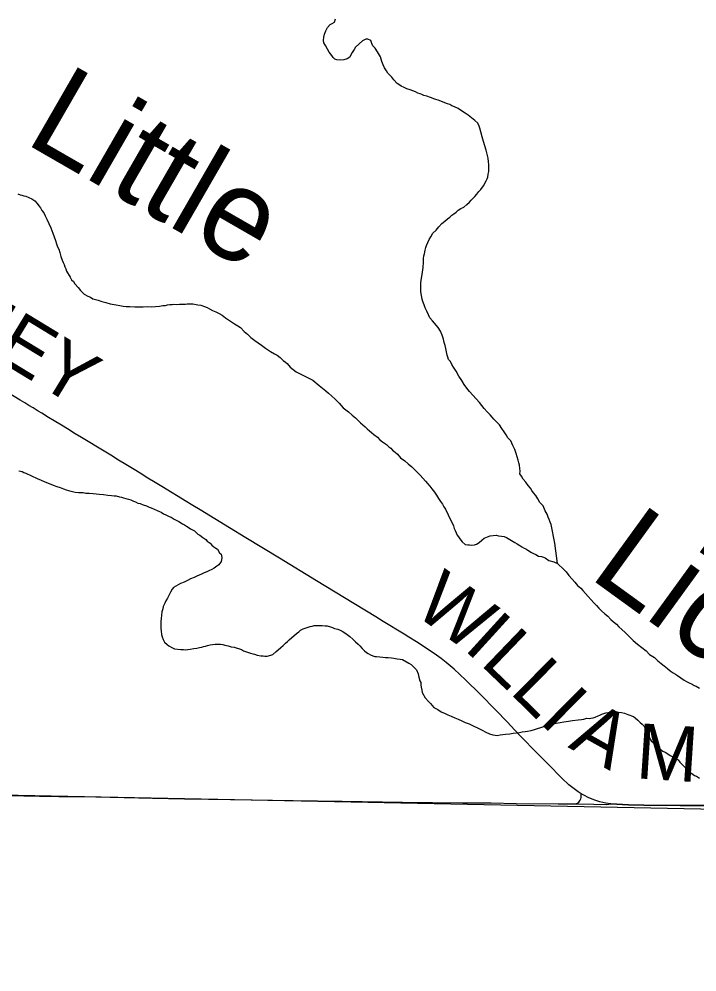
# Model space of a CAD drawing. Extents: x 0 to 34, y 0 to 22.
# Drawn here: x 5.756 to 6.454, y 15.275 to 16.256 of the extents above; entities that cross this region are included whole.
import ezdxf

# ---------------------------------------------------------------- set-up
doc = ezdxf.new("R2010")
doc.units = 0
for name, color, linetype in [('GM_X_County_Road', 7, 'Continuous'), ('GM_X_County_Road_Text', 7, 'Continuous'), ('GM_X_Minor_River', 7, 'Continuous'), ('GM_X_Minor_River_Text', 7, 'Continuous'), ('GM_X_Section', 7, 'Continuous'), ('GM_X_Township_Road', 7, 'Continuous')]:
    doc.layers.add(name, color=color, linetype=linetype)

msp = doc.modelspace()

# ---------------------------------------------------------------- linework, layer by layer
at = {"layer": 'GM_X_County_Road'}
for points in [[(6.33483, 15.45839), (6.33171, 15.46046), (6.32761, 15.46337), (6.32224, 15.46771), (6.31492, 15.47452), (6.3009, 15.48869), (6.28479, 15.50511), (6.27696, 15.51311), (6.27176, 15.51845), (6.26618, 15.52429), (6.26273, 15.52789), (6.25845, 15.53239), (6.24682, 15.54447), (6.23072, 15.56089), (6.21575, 15.57578), (6.2039, 15.58673), (6.19591, 15.59358), (6.19058, 15.59778), (6.18347, 15.60274), (6.16532, 15.61467), (6.1574, 15.61957), (6.15264, 15.6225), (6.13094, 15.63585), (6.1235, 15.64038), (6.09109, 15.66007), (6.06245, 15.67757), (6.02423, 15.70089), (5.98969, 15.72186), (5.97273, 15.73227), (5.94246, 15.75068), (5.93499, 15.75516), (5.92703, 15.76), (5.92012, 15.7642), (5.91219, 15.76909), (5.90475, 15.7736), (5.89628, 15.7788), (5.88886, 15.78336), (5.88092, 15.78824), (5.87455, 15.7921), (5.8661, 15.79735), (5.85868, 15.80189), (5.85073, 15.80676), (5.84383, 15.81096), (5.83534, 15.81614), (5.82896, 15.82), (5.82046, 15.82517), (5.81407, 15.82901), (5.8061, 15.83384), (5.79973, 15.83773), (5.79231, 15.84227), (5.78647, 15.84583), (5.77959, 15.85005), (5.77588, 15.85232), (5.77057, 15.85555), (5.76632, 15.8581), (5.76207, 15.86067), (5.75728, 15.86356), (5.72112, 15.88545)], [(5.621, 15.45844), (5.66541, 15.45788), (5.68717, 15.45771), (5.74498, 15.45665), (5.7773, 15.45592), (5.79719, 15.45568), (5.82082, 15.45543), (5.89354, 15.45403), (5.92648, 15.45322), (5.95134, 15.4527), (5.9961, 15.45214), (6.03837, 15.45131), (6.08872, 15.45092), (6.15088, 15.44988), (6.21305, 15.44908), (6.24227, 15.44895), (6.26775, 15.44848), (6.31127, 15.44811), (6.32904, 15.44791)], [(6.36524, 15.44799), (6.36004, 15.44883), (6.35391, 15.45026), (6.34792, 15.45217), (6.34211, 15.45459), (6.33824, 15.4566), (6.33483, 15.45839)], [(6.32904, 15.44791), (6.34795, 15.44764), (6.36076, 15.44734), (6.36315, 15.44759), (6.36524, 15.44799)], [(6.63564, 15.44407), (6.62493, 15.44411), (6.60569, 15.44445), (6.58518, 15.44447), (6.55657, 15.44478), (6.49876, 15.44583), (6.46705, 15.44615), (6.43659, 15.44644), (6.39929, 15.44676), (6.38362, 15.4471), (6.36524, 15.44799)]]:
    msp.add_lwpolyline(points, dxfattribs=at)
at = {"layer": 'GM_X_Minor_River'}
for points in [[(6.20369, 16.05524), (6.20601, 16.05709), (6.20833, 16.05893), (6.21103, 16.06077), (6.2141, 16.06221), (6.2172, 16.0648), (6.21992, 16.06739), (6.22148, 16.06926), (6.22342, 16.07111), (6.22536, 16.07296), (6.22732, 16.07557), (6.22928, 16.07818), (6.23161, 16.08041), (6.23318, 16.08265), (6.23475, 16.08451), (6.23556, 16.08677), (6.23714, 16.08939), (6.23794, 16.09127), (6.23874, 16.09316), (6.2392, 16.09618), (6.23964, 16.09883), (6.23969, 16.10111), (6.23976, 16.10414), (6.23981, 16.10604), (6.23949, 16.10871), (6.2392, 16.11252), (6.23816, 16.11672), (6.23712, 16.12092), (6.2357, 16.12513), (6.23429, 16.12973), (6.23289, 16.1347), (6.23148, 16.13967), (6.23044, 16.14349), (6.22972, 16.14541), (6.22828, 16.14848), (6.2253, 16.15121), (6.2186, 16.15669), (6.21524, 16.15905), (6.2115, 16.16142), (6.20813, 16.16378), (6.20437, 16.16538), (6.20175, 16.16659), (6.1995, 16.16778), (6.19724, 16.16859), (6.19272, 16.17022), (6.18858, 16.17184), (6.18407, 16.17347), (6.17955, 16.17509), (6.17578, 16.17632), (6.17276, 16.17716), (6.17088, 16.17796), (6.16901, 16.17876), (6.16675, 16.17958), (6.16412, 16.18078), (6.16149, 16.18198), (6.15885, 16.1828), (6.15546, 16.18402), (6.15245, 16.18523), (6.14945, 16.18682), (6.14721, 16.1884), (6.14534, 16.18958), (6.14201, 16.19308), (6.13979, 16.19579), (6.13758, 16.1985), (6.13572, 16.20007), (6.13425, 16.20238), (6.13243, 16.20546), (6.13098, 16.20854), (6.12954, 16.21199), (6.12814, 16.21696), (6.12522, 16.22197), (6.12266, 16.22583), (6.12043, 16.22816), (6.11935, 16.23046), (6.11828, 16.23353), (6.11528, 16.23512), (6.11301, 16.23517), (6.10955, 16.23336), (6.10255, 16.22669), (6.10098, 16.22444), (6.09902, 16.22145), (6.09781, 16.21882), (6.09662, 16.21657), (6.09392, 16.21474), (6.09048, 16.21368), (6.08668, 16.21339), (6.08327, 16.21385), (6.08139, 16.21465), (6.07953, 16.21622), (6.07806, 16.21815), (6.07548, 16.22163), (6.07365, 16.22471), (6.07147, 16.22856), (6.07001, 16.23126), (6.06969, 16.23355), (6.06977, 16.23696), (6.07061, 16.24036), (6.07183, 16.24375), (6.0738, 16.24712), (6.07653, 16.2501), (6.07845, 16.25119)], [(6.07845, 16.25119), (6.08077, 16.25265), (6.08198, 16.25604)], [(5.75505, 16.07579), (5.75731, 16.07498), (5.7592, 16.07456), (5.76108, 16.07375), (5.76335, 16.07332), (5.76636, 16.0721), (5.76937, 16.07089), (5.77235, 16.06854), (5.77494, 16.06582), (5.77641, 16.06351), (5.77826, 16.06156), (5.77971, 16.05887), (5.78155, 16.05617), (5.783, 16.0531), (5.78481, 16.04963), (5.78699, 16.0454), (5.78878, 16.0408), (5.79093, 16.03543), (5.79236, 16.0316), (5.79379, 16.02777), (5.79485, 16.02432), (5.79591, 16.02126), (5.797, 16.01895), (5.79806, 16.01551), (5.7991, 16.01131), (5.80053, 16.00747), (5.80161, 16.00517), (5.8027, 16.00324), (5.8034, 16.00057), (5.8045, 15.99864), (5.8052, 15.99635), (5.80885, 15.99018), (5.81031, 15.98749)], [(6.30782, 15.71634), (6.304, 15.73565), (6.30291, 15.73795), (6.30183, 15.74064), (6.30075, 15.74294), (6.29968, 15.74601), (6.29787, 15.74947), (6.29572, 15.75484), (6.29238, 15.75834), (6.29018, 15.76181), (6.28799, 15.76528), (6.28577, 15.76799), (6.28394, 15.7707), (6.28247, 15.77301), (6.28026, 15.77572), (6.27769, 15.7792), (6.2751, 15.7823), (6.27327, 15.78539), (6.27181, 15.7877), (6.27187, 15.79036), (6.27156, 15.79303), (6.27126, 15.79645), (6.27056, 15.79913), (6.26986, 15.8018), (6.2688, 15.80525), (6.26775, 15.80869), (6.26633, 15.8129), (6.26452, 15.81675), (6.26236, 15.82174), (6.2594, 15.82485), (6.25757, 15.82793), (6.25537, 15.83102), (6.25317, 15.83449), (6.25059, 15.83797), (6.24763, 15.84108), (6.24504, 15.8438), (6.24319, 15.84613), (6.24097, 15.84846), (6.238, 15.85157), (6.23505, 15.85506), (6.23026, 15.86125), (6.2199, 15.87251), (6.21694, 15.876), (6.21436, 15.87948), (6.2118, 15.88372), (6.20888, 15.88835), (6.20596, 15.89336), (6.2034, 15.8976), (6.20157, 15.9003), (6.20012, 15.90338), (6.19826, 15.90532), (6.19756, 15.90762), (6.19686, 15.90991), (6.19618, 15.91335), (6.1955, 15.91678), (6.19481, 15.91984), (6.19374, 15.9229), (6.19306, 15.92634), (6.19165, 15.93055), (6.18984, 15.93439), (6.18765, 15.93824), (6.18396, 15.94289), (6.18174, 15.94522), (6.17915, 15.94832), (6.17771, 15.9514), (6.1759, 15.95524), (6.17408, 15.9587), (6.17302, 15.96177), (6.17196, 15.96521), (6.17125, 15.96751), (6.17058, 15.97132), (6.16991, 15.97513), (6.1696, 15.9778), (6.16966, 15.98046), (6.16974, 15.98388), (6.17019, 15.9869), (6.17066, 15.99069), (6.17153, 15.99523), (6.17202, 16.00016), (6.17253, 16.00546), (6.17261, 16.00926), (6.17268, 16.01192), (6.17349, 16.01418), (6.17434, 16.01796), (6.17478, 16.0206), (6.17559, 16.02286), (6.17839, 16.02887), (6.17997, 16.0315), (6.18196, 16.03525), (6.18545, 16.03858), (6.18819, 16.04194), (6.1913, 16.04528), (6.1944, 16.04787), (6.19711, 16.05008), (6.19943, 16.05193), (6.20175, 16.05377), (6.20369, 16.05524)], [(5.81031, 15.98749), (5.81216, 15.98554), (5.81362, 15.98323), (5.81695, 15.97935), (5.81954, 15.97625), (5.82325, 15.97274), (5.82699, 15.97038), (5.82963, 15.96956), (5.83225, 15.96797), (5.83488, 15.96715), (5.83752, 15.96633), (5.84129, 15.9651), (5.84544, 15.96386), (5.84997, 15.96261), (5.85602, 15.96171), (5.85979, 15.96086), (5.8632, 15.9604), (5.86661, 15.95994), (5.8704, 15.95985), (5.87533, 15.95973), (5.87989, 15.95962), (5.88406, 15.95952), (5.88862, 15.9598), (5.89279, 15.9597), (5.8966, 15.95998), (5.90078, 15.96026), (5.90421, 15.96094), (5.90687, 15.96088), (5.90916, 15.96159), (5.91145, 15.96191), (5.91373, 15.96186), (5.91563, 15.96219), (5.91829, 15.96213), (5.92133, 15.96244), (5.92475, 15.96235), (5.9274, 15.96229), (5.92931, 15.96263), (5.93121, 15.96258), (5.9331, 15.96254), (5.935, 15.96249), (5.93841, 15.96203), (5.94029, 15.9616), (5.94332, 15.96115), (5.94709, 15.95992), (5.94972, 15.95872), (5.95235, 15.95752), (5.95535, 15.95593), (5.95873, 15.95433), (5.96211, 15.95273), (5.96511, 15.95114), (5.96884, 15.94839), (5.97369, 15.94486), (5.9778, 15.9421), (5.98155, 15.94011), (5.98416, 15.93815), (5.98787, 15.93426), (5.99122, 15.93152), (5.99493, 15.92801), (5.99904, 15.92488), (6.0024, 15.92252), (6.00576, 15.92016), (6.00986, 15.91702), (6.01509, 15.91348), (6.01921, 15.9111), (6.02184, 15.9099), (6.02482, 15.90755), (6.02817, 15.90443), (6.0304, 15.90248), (6.03227, 15.90129), (6.03522, 15.89742), (6.04156, 15.89271), (6.04756, 15.88953), (6.05169, 15.88754), (6.05582, 15.88554), (6.05844, 15.88395), (6.06068, 15.88238), (6.06291, 15.88043), (6.06514, 15.87848), (6.0685, 15.87574), (6.07185, 15.873), (6.07483, 15.87065), (6.0778, 15.86792), (6.08152, 15.86441), (6.0856, 15.86052), (6.08966, 15.85548), (6.09526, 15.85155), (6.09897, 15.84804), (6.10233, 15.8453), (6.1053, 15.84257), (6.10752, 15.84024), (6.11013, 15.83828), (6.11236, 15.83595), (6.11459, 15.83399), (6.11682, 15.83204), (6.11905, 15.83009), (6.12129, 15.82814), (6.12502, 15.82539), (6.12761, 15.82266), (6.13022, 15.8207), (6.13246, 15.81913), (6.13433, 15.81795)], [(6.13433, 15.81795), (6.13694, 15.81561), (6.1388, 15.81404), (6.14065, 15.8121), (6.14326, 15.81014), (6.14586, 15.8078), (6.14882, 15.80431), (6.1533, 15.80116), (6.15664, 15.79804), (6.16037, 15.79491), (6.1689, 15.78635), (6.17186, 15.78324), (6.17444, 15.78014), (6.17667, 15.77781), (6.17888, 15.7751), (6.1811, 15.77238), (6.18367, 15.76891), (6.18588, 15.76581), (6.18807, 15.76234), (6.1899, 15.75926), (6.19211, 15.75655), (6.19357, 15.75385), (6.19503, 15.75116), (6.19611, 15.74885), (6.19757, 15.74654), (6.19829, 15.74462), (6.19974, 15.74193), (6.20081, 15.73886), (6.20227, 15.73655), (6.20336, 15.73424), (6.20405, 15.73157), (6.20514, 15.72926), (6.20622, 15.72696), (6.20731, 15.72465), (6.2084, 15.72273), (6.20988, 15.72079), (6.21246, 15.71769), (6.21544, 15.71496), (6.21808, 15.71452), (6.21998, 15.71447), (6.22226, 15.71442), (6.22492, 15.71473), (6.22721, 15.71544), (6.2299, 15.7169), (6.23262, 15.71949), (6.23494, 15.72134), (6.2384, 15.72277), (6.24108, 15.72385), (6.24412, 15.72416), (6.24717, 15.72446), (6.24981, 15.72402), (6.25284, 15.72357), (6.25549, 15.72313), (6.25775, 15.72231), (6.25962, 15.72113), (6.26636, 15.71717), (6.26898, 15.71559), (6.2716, 15.714), (6.27384, 15.71243), (6.27609, 15.71124), (6.27797, 15.71043), (6.27984, 15.70925), (6.28358, 15.70688), (6.28583, 15.70569), (6.28808, 15.70449), (6.2907, 15.70291), (6.2941, 15.70245), (6.29599, 15.70202), (6.29787, 15.70122), (6.3016, 15.69847), (6.30651, 15.69721), (6.31026, 15.69523), (6.31696, 15.68937), (6.31917, 15.68666), (6.32212, 15.68317), (6.32545, 15.67929), (6.32841, 15.67618), (6.33099, 15.6727), (6.33434, 15.66996), (6.33656, 15.66763), (6.33915, 15.66452), (6.34211, 15.66141), (6.34507, 15.65792), (6.34765, 15.65482), (6.35063, 15.65209), (6.35284, 15.64938), (6.35581, 15.64665), (6.35916, 15.64353), (6.36214, 15.64118), (6.36547, 15.63768), (6.36808, 15.63534), (6.37106, 15.63299), (6.37365, 15.63027), (6.37662, 15.62754), (6.37997, 15.62442), (6.38367, 15.62053), (6.38813, 15.61625), (6.39259, 15.61234), (6.39706, 15.60882), (6.40154, 15.60567), (6.40525, 15.60178)], [(5.75596, 15.79085), (5.75935, 15.79001), (5.76123, 15.78921), (5.76311, 15.7884), (5.77475, 15.78281), (5.77889, 15.78119), (5.78265, 15.77958), (5.78715, 15.77757), (5.79129, 15.77595), (5.79506, 15.77473), (5.79845, 15.77351), (5.80184, 15.77228), (5.80485, 15.77107), (5.80711, 15.77064), (5.80937, 15.76983), (5.81126, 15.7694), (5.81391, 15.76896), (5.81731, 15.7685), (5.81921, 15.76845), (5.82225, 15.76838), (5.82489, 15.76794), (5.82831, 15.76786), (5.83247, 15.76738), (5.83853, 15.76685), (5.84308, 15.76637), (5.84762, 15.76588), (5.85141, 15.76541), (5.85405, 15.76497)], [(5.85405, 15.76497), (5.85633, 15.76491), (5.85973, 15.76407), (5.86162, 15.76365), (5.86387, 15.76283), (5.86614, 15.7624), (5.86878, 15.76158), (5.87142, 15.76076), (5.87405, 15.75955), (5.87593, 15.75875), (5.87856, 15.75755), (5.88083, 15.75711), (5.88383, 15.7559), (5.88722, 15.75468), (5.89023, 15.75347), (5.89211, 15.75266), (5.8985, 15.74985), (5.90076, 15.74904), (5.90264, 15.74823), (5.90488, 15.74666), (5.90713, 15.74547), (5.91088, 15.74386), (5.91276, 15.74306), (5.91576, 15.74109), (5.91801, 15.73989), (5.92064, 15.73869), (5.92437, 15.73632), (5.92662, 15.73513), (5.9285, 15.73395), (5.93037, 15.73276), (5.93261, 15.73119), (5.93486, 15.72999), (5.93674, 15.72919), (5.94007, 15.72569), (5.94232, 15.7245), (5.9453, 15.72215), (5.94829, 15.72018), (5.94977, 15.71824), (5.95276, 15.71627), (5.95461, 15.71433), (5.95684, 15.71238), (5.95871, 15.71119), (5.96058, 15.71001), (5.9624, 15.70654), (5.96426, 15.70498), (5.96494, 15.70154), (5.96451, 15.69927), (5.96408, 15.69739), (5.96172, 15.69402), (5.95979, 15.69255), (5.95709, 15.69071), (5.95478, 15.68925), (5.95171, 15.6878), (5.9494, 15.68672), (5.94672, 15.68564), (5.94404, 15.68456), (5.94174, 15.68348), (5.93905, 15.68241), (5.93636, 15.68095), (5.93253, 15.67952), (5.92946, 15.67807), (5.926, 15.67626), (5.92255, 15.67482), (5.91986, 15.67336), (5.91755, 15.6719), (5.91525, 15.67081), (5.91368, 15.66895), (5.91209, 15.66595), (5.9105, 15.66257), (5.90891, 15.65956), (5.90733, 15.65694), (5.90613, 15.65469), (5.90454, 15.65131), (5.90409, 15.64866), (5.90326, 15.64564), (5.9028, 15.64223), (5.90234, 15.63882), (5.90227, 15.63579), (5.90218, 15.63199), (5.90211, 15.62895), (5.90242, 15.62591), (5.90272, 15.62248), (5.90342, 15.6198), (5.90449, 15.61712), (5.90595, 15.61442), (5.90855, 15.61208), (5.91041, 15.61052), (5.91416, 15.60853), (5.91604, 15.60773), (5.92285, 15.6068), (5.92551, 15.60674), (5.92778, 15.60669), (5.93007, 15.60701), (5.93236, 15.60734), (5.93617, 15.60801), (5.93921, 15.60831), (5.94189, 15.60901), (5.94417, 15.60934), (5.94609, 15.61005), (5.94799, 15.61038), (5.95029, 15.61109)], [(6.31026, 15.69523), (6.30782, 15.71634)], [(5.95029, 15.61109), (5.95296, 15.61179), (5.95525, 15.61211), (5.95791, 15.61243), (5.96057, 15.61237), (5.9636, 15.61229), (5.96587, 15.61186), (5.96814, 15.61143), (5.97154, 15.61059), (5.97455, 15.60975), (5.97758, 15.6093), (5.97984, 15.60849), (5.98323, 15.60765), (5.98512, 15.60684), (5.98736, 15.60565), (5.99037, 15.60444), (5.99452, 15.6032), (5.99678, 15.60239), (5.99867, 15.60196), (6.0013, 15.60114), (6.00508, 15.60029), (6.00736, 15.60024), (6.00926, 15.60019), (6.01153, 15.60014), (6.01535, 15.60119), (6.01727, 15.6019), (6.02075, 15.60486), (6.02307, 15.6067), (6.02578, 15.60892), (6.02812, 15.61114), (6.03044, 15.61336), (6.03239, 15.61522), (6.03432, 15.61669), (6.04169, 15.62336), (6.04401, 15.6252), (6.04594, 15.62667), (6.04863, 15.62813), (6.0559, 15.63062), (6.05781, 15.63095), (6.06011, 15.63166), (6.062, 15.63161), (6.0658, 15.63152), (6.06807, 15.63147), (6.07111, 15.63139), (6.07338, 15.63134), (6.07677, 15.63012), (6.07866, 15.62969), (6.08091, 15.6285), (6.08431, 15.62766), (6.08657, 15.62685), (6.08882, 15.62565), (6.09144, 15.62407), (6.09406, 15.62249), (6.09666, 15.62015), (6.09963, 15.61742), (6.10261, 15.61469), (6.10521, 15.61235), (6.10707, 15.61078), (6.10928, 15.60807), (6.11188, 15.60535), (6.11374, 15.60378), (6.11561, 15.6026), (6.11786, 15.60141), (6.12049, 15.6002), (6.12238, 15.59978), (6.12427, 15.59973), (6.12768, 15.59927), (6.13071, 15.59882), (6.13336, 15.59876), (6.13602, 15.5987), (6.13942, 15.59823), (6.14207, 15.59779), (6.14548, 15.59733), (6.1485, 15.59688), (6.15077, 15.59645), (6.15752, 15.59287), (6.15976, 15.59129), (6.16199, 15.58934), (6.16533, 15.58584), (6.16714, 15.582), (6.16781, 15.57856), (6.16886, 15.57474), (6.16958, 15.57282), (6.1699, 15.57053), (6.17023, 15.56825), (6.17092, 15.56519), (6.17123, 15.56252), (6.17415, 15.55714), (6.17784, 15.55287), (6.1797, 15.55131), (6.18302, 15.54705), (6.18715, 15.54505), (6.19051, 15.54269), (6.19465, 15.54107), (6.19765, 15.53948), (6.20103, 15.53826), (6.20479, 15.53665), (6.20817, 15.53505), (6.21193, 15.53344), (6.21531, 15.53184), (6.21945, 15.53022)], [(6.40525, 15.60178), (6.41011, 15.59863), (6.41383, 15.59512), (6.41718, 15.59238), (6.42016, 15.59003), (6.42351, 15.58729), (6.42649, 15.58494), (6.42949, 15.58297), (6.43172, 15.58139), (6.43398, 15.5802), (6.43734, 15.57784), (6.4407, 15.57548), (6.44332, 15.5739), (6.44595, 15.5727), (6.44895, 15.57111), (6.4512, 15.56991), (6.45308, 15.56911), (6.45645, 15.56713)], [(6.21945, 15.53022), (6.22358, 15.52822), (6.22883, 15.52582), (6.23296, 15.52382), (6.23671, 15.52183), (6.24047, 15.52022), (6.24386, 15.519), (6.24613, 15.51857), (6.2484, 15.51852), (6.25146, 15.5192), (6.25679, 15.51984), (6.26135, 15.52011), (6.26478, 15.52078), (6.26821, 15.52108), (6.27125, 15.52139), (6.27392, 15.52209), (6.27697, 15.52239), (6.27963, 15.52271), (6.28345, 15.52338), (6.28689, 15.52444), (6.28995, 15.5255), (6.29339, 15.52656), (6.29722, 15.52799), (6.30104, 15.52904), (6.30486, 15.53009), (6.30906, 15.53113), (6.31326, 15.53179), (6.31707, 15.53246), (6.32164, 15.53311), (6.32583, 15.53377), (6.33154, 15.53439), (6.33496, 15.53469), (6.33763, 15.53501), (6.34069, 15.53607), (6.34297, 15.53602), (6.34487, 15.53635), (6.34716, 15.53668), (6.34907, 15.53739), (6.35213, 15.53846), (6.35405, 15.53917), (6.35597, 15.54027), (6.35827, 15.54097), (6.36018, 15.54169), (6.36247, 15.54201), (6.36514, 15.54271), (6.3678, 15.54265), (6.37046, 15.54296), (6.37311, 15.54252), (6.37614, 15.54207), (6.37953, 15.54123), (6.38292, 15.54001), (6.38857, 15.53797), (6.39043, 15.53641), (6.39303, 15.53407), (6.39563, 15.53173), (6.39749, 15.53016), (6.39935, 15.52822), (6.40224, 15.52207), (6.4044, 15.51708), (6.40696, 15.51284), (6.40919, 15.51088), (6.41029, 15.50896), (6.41326, 15.50623), (6.41512, 15.50466), (6.41699, 15.50348), (6.41886, 15.5023), (6.42111, 15.5011), (6.42411, 15.49951), (6.42635, 15.49794), (6.4286, 15.49674), (6.4316, 15.49515), (6.43459, 15.49318), (6.43643, 15.49086), (6.4394, 15.48775), (6.44199, 15.48503), (6.44384, 15.48308), (6.44608, 15.48113), (6.44869, 15.47917), (6.4513, 15.47721), (6.45356, 15.47639), (6.45655, 15.47442)]]:
    msp.add_lwpolyline(points, dxfattribs=at)
at = {"layer": 'GM_X_Section'}
msp.add_lwpolyline([(5.61786, 15.45978), (6.62912, 15.43932), (6.61504, 14.44194), (5.60488, 14.4601)], close=True, dxfattribs=at)
at = {"layer": 'GM_X_Township_Road'}
for points in [[(5.621, 15.45844), (5.66541, 15.45788), (5.68717, 15.45771), (5.74498, 15.45665), (5.7773, 15.45592), (5.79719, 15.45568), (5.82082, 15.45543), (5.89354, 15.45403), (5.92648, 15.45322), (5.95134, 15.4527), (5.9961, 15.45214), (6.03837, 15.45131), (6.08872, 15.45092), (6.15088, 15.44988), (6.21305, 15.44908), (6.24227, 15.44895), (6.26775, 15.44848), (6.31127, 15.44811), (6.32904, 15.44791)], [(6.32904, 15.44791), (6.33099, 15.44875), (6.33224, 15.44975), (6.33308, 15.45069), (6.33379, 15.45188), (6.33437, 15.45325), (6.33471, 15.45451), (6.33491, 15.45568), (6.33491, 15.45696), (6.33483, 15.45839)], [(6.32904, 15.44791), (6.34795, 15.44764), (6.36076, 15.44734), (6.36315, 15.44759), (6.36524, 15.44799)], [(6.36524, 15.44799), (6.38362, 15.4471), (6.39929, 15.44676), (6.43659, 15.44644), (6.46705, 15.44615), (6.49876, 15.44583), (6.55657, 15.44478), (6.58518, 15.44447), (6.60569, 15.44445), (6.62493, 15.44411), (6.63564, 15.44407)]]:
    msp.add_lwpolyline(points, dxfattribs=at)

# ---------------------------------------------------------------- texts
at = {"layer": 'GM_X_County_Road_Text'}
for s, height, rotation, p in [('NEY', 0.056818, 328.69021, (5.68165, 15.93648)), ('W', 0.05682, 324.33368, (6.16068, 15.64495)), ('I', 0.05682, 317.66829, (6.21281, 15.60766)), ('L', 0.05682, 316.16754, (6.22977, 15.59222)), ('L', 0.05682, 315.23865, (6.26025, 15.56295)), ('I', 0.05682, 315.35544, (6.29052, 15.53294)), ('A', 0.05682, 330.83239, (6.32048, 15.50651)), ('M', 0.05682, 356.22481, (6.3903, 15.47441))]:
    msp.add_text(s, height=height, rotation=rotation, dxfattribs=at).set_placement(p)
at = {"layer": 'GM_X_Minor_River_Text'}
for s, height, rotation, p in [('Little', 0.094754, 330.04616, (5.76031, 16.12914)), ('Lick', 0.094759, 324.04129, (6.34113, 15.6821))]:
    msp.add_text(s, height=height, rotation=rotation, dxfattribs=at).set_placement(p)

doc.saveas('drawing.dxf')
